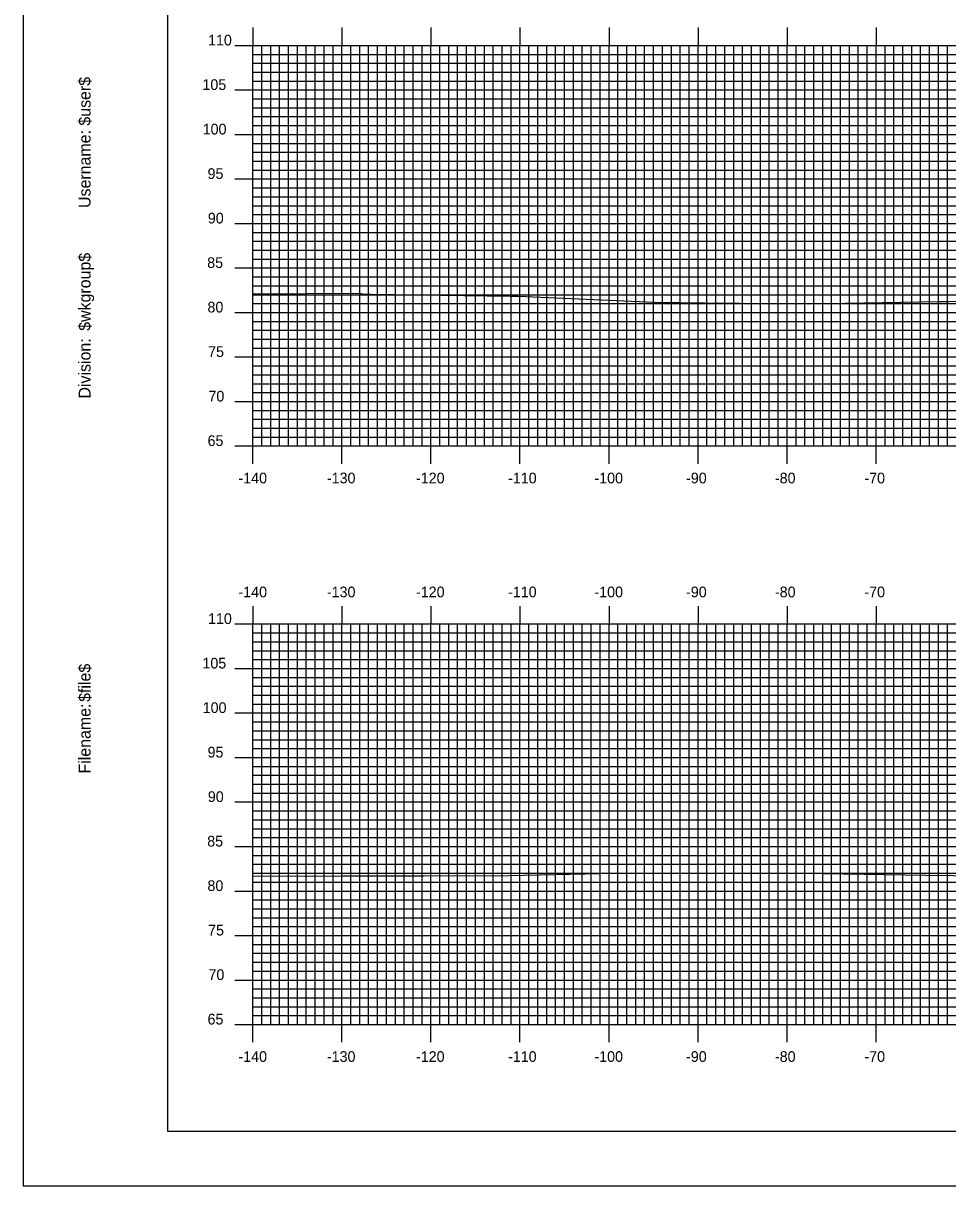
# Model space of a CAD drawing. Extents: x 857504 to 857847, y 364765 to 364985.
# Drawn here: x 857503.5 to 857607.4, y 364765.2 to 364895.8 of the extents above; entities that cross this region are included whole.
import ezdxf

# ---------------------------------------------------------------- set-up
doc = ezdxf.new("R2010")
doc.units = 0
for name, color, linetype in [('BORDER', 7, 'Continuous'), ('D_Roadway_Centerline', 7, 'Continuous'), ('H_V ANNOTATION', 7, 'Continuous'), ('MAJOR', 7, 'Continuous'), ('MINOR', 7, 'Continuous'), ('PLOT BOUNDARY', 7, 'Continuous'), ('S_Roadway_Centerline', 7, 'Continuous')]:
    doc.layers.add(name, color=color, linetype=linetype)

msp = doc.modelspace()

# ---------------------------------------------------------------- linework, layer by layer
at = {"layer": 'BORDER'}
msp.add_lwpolyline([(857519.71, 364771.3), (857839.71, 364771.3), (857839.71, 364981.3), (857519.71, 364981.3)], close=True, dxfattribs=at)
at = {"layer": 'MAJOR'}
for p, q in [((857529.31, 364895.31), (857529.31, 364893.3)), ((857539.31, 364895.31), (857539.31, 364893.3)), ((857549.31, 364895.31), (857549.31, 364893.3)), ((857559.31, 364895.31), (857559.31, 364893.3)), ((857569.31, 364895.31), (857569.31, 364893.3)), ((857579.31, 364895.31), (857579.31, 364893.3)), ((857589.31, 364895.31), (857589.31, 364893.3)), ((857599.31, 364895.31), (857599.31, 364893.3)), ((857527.3, 364893.3), (857529.31, 364893.3)), ((857529.31, 364893.3), (857809.31, 364893.3)), ((857529.31, 364848.3), (857529.31, 364893.3)), ((857529.31, 364848.3), (857529.31, 364893.3)), ((857529.31, 364893.3), (857809.31, 364893.3)), ((857539.31, 364848.3), (857539.31, 364893.3)), ((857549.31, 364848.3), (857549.31, 364893.3)), ((857559.31, 364848.3), (857559.31, 364893.3)), ((857569.31, 364848.3), (857569.31, 364893.3)), ((857579.31, 364848.3), (857579.31, 364893.3)), ((857589.31, 364848.3), (857589.31, 364893.3)), ((857599.31, 364848.3), (857599.31, 364893.3)), ((857527.3, 364888.3), (857529.31, 364888.3)), ((857529.31, 364888.3), (857809.31, 364888.3)), ((857527.3, 364883.3), (857529.31, 364883.3)), ((857529.31, 364883.3), (857809.31, 364883.3)), ((857527.3, 364878.3), (857529.31, 364878.3)), ((857529.31, 364878.3), (857809.31, 364878.3)), ((857527.3, 364873.3), (857529.31, 364873.3)), ((857529.31, 364873.3), (857809.31, 364873.3)), ((857527.3, 364868.3), (857529.31, 364868.3)), ((857529.31, 364868.3), (857809.31, 364868.3)), ((857527.3, 364863.3), (857529.31, 364863.3)), ((857529.31, 364863.3), (857809.31, 364863.3)), ((857527.3, 364858.3), (857529.31, 364858.3)), ((857529.31, 364858.3), (857809.31, 364858.3)), ((857527.3, 364853.3), (857529.31, 364853.3)), ((857529.31, 364853.3), (857809.31, 364853.3)), ((857527.3, 364848.3), (857529.31, 364848.3)), ((857529.31, 364848.3), (857809.31, 364848.3)), ((857529.31, 364848.3), (857809.31, 364848.3)), ((857529.31, 364846.3), (857529.31, 364848.3)), ((857539.31, 364846.3), (857539.31, 364848.3)), ((857549.31, 364846.3), (857549.31, 364848.3)), ((857559.31, 364846.3), (857559.31, 364848.3)), ((857569.31, 364846.3), (857569.31, 364848.3)), ((857579.31, 364846.3), (857579.31, 364848.3)), ((857589.31, 364846.3), (857589.31, 364848.3)), ((857599.31, 364846.3), (857599.31, 364848.3)), ((857529.31, 364830.31), (857529.31, 364828.3)), ((857539.31, 364830.31), (857539.31, 364828.3)), ((857549.31, 364830.31), (857549.31, 364828.3)), ((857559.31, 364830.31), (857559.31, 364828.3)), ((857569.31, 364830.31), (857569.31, 364828.3)), ((857579.31, 364830.31), (857579.31, 364828.3)), ((857589.31, 364830.31), (857589.31, 364828.3)), ((857599.31, 364830.31), (857599.31, 364828.3)), ((857527.3, 364828.3), (857529.31, 364828.3)), ((857529.31, 364828.3), (857809.31, 364828.3)), ((857529.31, 364783.3), (857529.31, 364828.3)), ((857529.31, 364783.3), (857529.31, 364828.3)), ((857529.31, 364828.3), (857809.31, 364828.3)), ((857539.31, 364783.3), (857539.31, 364828.3)), ((857549.31, 364783.3), (857549.31, 364828.3)), ((857559.31, 364783.3), (857559.31, 364828.3)), ((857569.31, 364783.3), (857569.31, 364828.3)), ((857579.31, 364783.3), (857579.31, 364828.3)), ((857589.31, 364783.3), (857589.31, 364828.3)), ((857599.31, 364783.3), (857599.31, 364828.3)), ((857527.3, 364823.3), (857529.31, 364823.3)), ((857529.31, 364823.3), (857809.31, 364823.3)), ((857527.3, 364818.3), (857529.31, 364818.3)), ((857529.31, 364818.3), (857809.31, 364818.3)), ((857527.3, 364813.3), (857529.31, 364813.3)), ((857529.31, 364813.3), (857809.31, 364813.3)), ((857527.3, 364808.3), (857529.31, 364808.3)), ((857529.31, 364808.3), (857809.31, 364808.3)), ((857527.3, 364803.3), (857529.31, 364803.3)), ((857529.31, 364803.3), (857809.31, 364803.3)), ((857527.3, 364798.3), (857529.31, 364798.3)), ((857529.31, 364798.3), (857809.31, 364798.3)), ((857527.3, 364793.3), (857529.31, 364793.3)), ((857529.31, 364793.3), (857809.31, 364793.3)), ((857527.3, 364788.3), (857529.31, 364788.3)), ((857529.31, 364788.3), (857809.31, 364788.3)), ((857527.3, 364783.3), (857529.31, 364783.3)), ((857529.31, 364783.3), (857809.31, 364783.3)), ((857529.31, 364783.3), (857809.31, 364783.3)), ((857529.31, 364781.3), (857529.31, 364783.3)), ((857539.31, 364781.3), (857539.31, 364783.3)), ((857549.31, 364781.3), (857549.31, 364783.3)), ((857559.31, 364781.3), (857559.31, 364783.3)), ((857569.31, 364781.3), (857569.31, 364783.3)), ((857579.31, 364781.3), (857579.31, 364783.3)), ((857589.31, 364781.3), (857589.31, 364783.3)), ((857599.31, 364781.3), (857599.31, 364783.3))]:
    msp.add_line(p, q, dxfattribs=at)
at = {"layer": 'MINOR'}
for p, q in [((857530.31, 364848.3), (857530.31, 364893.3)), ((857531.31, 364848.3), (857531.31, 364893.3)), ((857532.31, 364848.3), (857532.31, 364893.3)), ((857533.31, 364848.3), (857533.31, 364893.3)), ((857534.31, 364848.3), (857534.31, 364893.3)), ((857535.31, 364848.3), (857535.31, 364893.3)), ((857536.31, 364848.3), (857536.31, 364893.3)), ((857537.31, 364848.3), (857537.31, 364893.3)), ((857538.31, 364848.3), (857538.31, 364893.3)), ((857540.31, 364848.3), (857540.31, 364893.3)), ((857541.31, 364848.3), (857541.31, 364893.3)), ((857542.31, 364848.3), (857542.31, 364893.3)), ((857543.31, 364848.3), (857543.31, 364893.3)), ((857544.31, 364848.3), (857544.31, 364893.3)), ((857545.31, 364848.3), (857545.31, 364893.3)), ((857546.31, 364848.3), (857546.31, 364893.3)), ((857547.31, 364848.3), (857547.31, 364893.3)), ((857548.31, 364848.3), (857548.31, 364893.3)), ((857550.31, 364848.3), (857550.31, 364893.3)), ((857551.31, 364848.3), (857551.31, 364893.3)), ((857552.31, 364848.3), (857552.31, 364893.3)), ((857553.31, 364848.3), (857553.31, 364893.3)), ((857554.31, 364848.3), (857554.31, 364893.3)), ((857555.31, 364848.3), (857555.31, 364893.3)), ((857556.31, 364848.3), (857556.31, 364893.3)), ((857557.31, 364848.3), (857557.31, 364893.3)), ((857558.31, 364848.3), (857558.31, 364893.3)), ((857560.31, 364848.3), (857560.31, 364893.3)), ((857561.31, 364848.3), (857561.31, 364893.3)), ((857562.31, 364848.3), (857562.31, 364893.3)), ((857563.31, 364848.3), (857563.31, 364893.3)), ((857564.31, 364848.3), (857564.31, 364893.3)), ((857565.31, 364848.3), (857565.31, 364893.3)), ((857566.31, 364848.3), (857566.31, 364893.3)), ((857567.31, 364848.3), (857567.31, 364893.3)), ((857568.31, 364848.3), (857568.31, 364893.3)), ((857570.31, 364848.3), (857570.31, 364893.3)), ((857571.31, 364848.3), (857571.31, 364893.3)), ((857572.31, 364848.3), (857572.31, 364893.3)), ((857573.31, 364848.3), (857573.31, 364893.3)), ((857574.31, 364848.3), (857574.31, 364893.3)), ((857575.31, 364848.3), (857575.31, 364893.3)), ((857576.31, 364848.3), (857576.31, 364893.3)), ((857577.31, 364848.3), (857577.31, 364893.3)), ((857578.31, 364848.3), (857578.31, 364893.3)), ((857580.31, 364848.3), (857580.31, 364893.3)), ((857581.31, 364848.3), (857581.31, 364893.3)), ((857582.31, 364848.3), (857582.31, 364893.3)), ((857583.31, 364848.3), (857583.31, 364893.3)), ((857584.31, 364848.3), (857584.31, 364893.3)), ((857585.31, 364848.3), (857585.31, 364893.3)), ((857586.31, 364848.3), (857586.31, 364893.3)), ((857587.31, 364848.3), (857587.31, 364893.3)), ((857588.31, 364848.3), (857588.31, 364893.3)), ((857590.31, 364848.3), (857590.31, 364893.3)), ((857591.31, 364848.3), (857591.31, 364893.3)), ((857592.31, 364848.3), (857592.31, 364893.3)), ((857593.31, 364848.3), (857593.31, 364893.3)), ((857594.31, 364848.3), (857594.31, 364893.3)), ((857595.31, 364848.3), (857595.31, 364893.3)), ((857596.31, 364848.3), (857596.31, 364893.3)), ((857597.31, 364848.3), (857597.31, 364893.3)), ((857598.31, 364848.3), (857598.31, 364893.3)), ((857600.31, 364848.3), (857600.31, 364893.3)), ((857601.31, 364848.3), (857601.31, 364893.3)), ((857602.31, 364848.3), (857602.31, 364893.3)), ((857603.31, 364848.3), (857603.31, 364893.3)), ((857604.31, 364848.3), (857604.31, 364893.3)), ((857605.31, 364848.3), (857605.31, 364893.3)), ((857606.31, 364848.3), (857606.31, 364893.3)), ((857607.31, 364848.3), (857607.31, 364893.3)), ((857529.31, 364892.3), (857809.31, 364892.3)), ((857529.31, 364892.3), (857531.31, 364892.3)), ((857529.31, 364891.3), (857809.31, 364891.3)), ((857529.31, 364891.3), (857531.31, 364891.3)), ((857529.31, 364890.3), (857809.31, 364890.3)), ((857529.31, 364890.3), (857531.31, 364890.3)), ((857529.31, 364889.3), (857809.31, 364889.3)), ((857529.31, 364889.3), (857531.31, 364889.3)), ((857529.31, 364887.3), (857809.31, 364887.3)), ((857529.31, 364887.3), (857531.31, 364887.3)), ((857529.31, 364886.3), (857809.31, 364886.3)), ((857529.31, 364886.3), (857531.31, 364886.3)), ((857529.31, 364885.3), (857809.31, 364885.3)), ((857529.31, 364885.3), (857531.31, 364885.3)), ((857529.31, 364884.3), (857809.31, 364884.3)), ((857529.31, 364884.3), (857531.31, 364884.3)), ((857529.31, 364882.3), (857809.31, 364882.3)), ((857529.31, 364882.3), (857531.31, 364882.3)), ((857529.31, 364881.3), (857809.31, 364881.3)), ((857529.31, 364881.3), (857531.31, 364881.3)), ((857529.31, 364880.3), (857809.31, 364880.3)), ((857529.31, 364880.3), (857531.31, 364880.3)), ((857529.31, 364879.3), (857809.31, 364879.3)), ((857529.31, 364879.3), (857531.31, 364879.3)), ((857529.31, 364877.3), (857809.31, 364877.3)), ((857529.31, 364877.3), (857531.31, 364877.3)), ((857529.31, 364876.3), (857809.31, 364876.3)), ((857529.31, 364876.3), (857531.31, 364876.3)), ((857529.31, 364875.3), (857809.31, 364875.3)), ((857529.31, 364875.3), (857531.31, 364875.3)), ((857529.31, 364874.3), (857809.31, 364874.3)), ((857529.31, 364874.3), (857531.31, 364874.3)), ((857529.31, 364872.3), (857809.31, 364872.3)), ((857529.31, 364872.3), (857531.31, 364872.3)), ((857529.31, 364871.3), (857809.31, 364871.3)), ((857529.31, 364871.3), (857531.31, 364871.3)), ((857529.31, 364870.3), (857809.31, 364870.3)), ((857529.31, 364870.3), (857531.31, 364870.3)), ((857529.31, 364869.3), (857809.31, 364869.3)), ((857529.31, 364869.3), (857531.31, 364869.3)), ((857529.31, 364867.3), (857809.31, 364867.3)), ((857529.31, 364867.3), (857531.31, 364867.3)), ((857529.31, 364866.3), (857809.31, 364866.3)), ((857529.31, 364866.3), (857531.31, 364866.3)), ((857529.31, 364865.3), (857809.31, 364865.3)), ((857529.31, 364865.3), (857531.31, 364865.3)), ((857529.31, 364864.3), (857809.31, 364864.3)), ((857529.31, 364864.3), (857531.31, 364864.3)), ((857529.31, 364862.3), (857809.31, 364862.3)), ((857529.31, 364862.3), (857531.31, 364862.3)), ((857529.31, 364861.3), (857809.31, 364861.3)), ((857529.31, 364861.3), (857531.31, 364861.3)), ((857529.31, 364860.3), (857809.31, 364860.3)), ((857529.31, 364860.3), (857531.31, 364860.3)), ((857529.31, 364859.3), (857809.31, 364859.3)), ((857529.31, 364859.3), (857531.31, 364859.3)), ((857529.31, 364857.3), (857809.31, 364857.3)), ((857529.31, 364857.3), (857531.31, 364857.3)), ((857529.31, 364856.3), (857809.31, 364856.3)), ((857529.31, 364856.3), (857531.31, 364856.3)), ((857529.31, 364855.3), (857809.31, 364855.3)), ((857529.31, 364855.3), (857531.31, 364855.3)), ((857529.31, 364854.3), (857809.31, 364854.3)), ((857529.31, 364854.3), (857531.31, 364854.3)), ((857529.31, 364852.3), (857809.31, 364852.3)), ((857529.31, 364852.3), (857531.31, 364852.3)), ((857529.31, 364851.3), (857809.31, 364851.3)), ((857529.31, 364851.3), (857531.31, 364851.3)), ((857529.31, 364850.3), (857809.31, 364850.3)), ((857529.31, 364850.3), (857531.31, 364850.3)), ((857529.31, 364849.3), (857809.31, 364849.3)), ((857529.31, 364849.3), (857531.31, 364849.3)), ((857530.31, 364783.3), (857530.31, 364828.3)), ((857531.31, 364783.3), (857531.31, 364828.3)), ((857532.31, 364783.3), (857532.31, 364828.3)), ((857533.31, 364783.3), (857533.31, 364828.3)), ((857534.31, 364783.3), (857534.31, 364828.3)), ((857535.31, 364783.3), (857535.31, 364828.3)), ((857536.31, 364783.3), (857536.31, 364828.3)), ((857537.31, 364783.3), (857537.31, 364828.3)), ((857538.31, 364783.3), (857538.31, 364828.3)), ((857540.31, 364783.3), (857540.31, 364828.3)), ((857541.31, 364783.3), (857541.31, 364828.3)), ((857542.31, 364783.3), (857542.31, 364828.3)), ((857543.31, 364783.3), (857543.31, 364828.3)), ((857544.31, 364783.3), (857544.31, 364828.3)), ((857545.31, 364783.3), (857545.31, 364828.3)), ((857546.31, 364783.3), (857546.31, 364828.3)), ((857547.31, 364783.3), (857547.31, 364828.3)), ((857548.31, 364783.3), (857548.31, 364828.3)), ((857550.31, 364783.3), (857550.31, 364828.3)), ((857551.31, 364783.3), (857551.31, 364828.3)), ((857552.31, 364783.3), (857552.31, 364828.3)), ((857553.31, 364783.3), (857553.31, 364828.3)), ((857554.31, 364783.3), (857554.31, 364828.3)), ((857555.31, 364783.3), (857555.31, 364828.3)), ((857556.31, 364783.3), (857556.31, 364828.3)), ((857557.31, 364783.3), (857557.31, 364828.3)), ((857558.31, 364783.3), (857558.31, 364828.3)), ((857560.31, 364783.3), (857560.31, 364828.3)), ((857561.31, 364783.3), (857561.31, 364828.3)), ((857562.31, 364783.3), (857562.31, 364828.3)), ((857563.31, 364783.3), (857563.31, 364828.3)), ((857564.31, 364783.3), (857564.31, 364828.3)), ((857565.31, 364783.3), (857565.31, 364828.3)), ((857566.31, 364783.3), (857566.31, 364828.3)), ((857567.31, 364783.3), (857567.31, 364828.3)), ((857568.31, 364783.3), (857568.31, 364828.3)), ((857570.31, 364783.3), (857570.31, 364828.3)), ((857571.31, 364783.3), (857571.31, 364828.3)), ((857572.31, 364783.3), (857572.31, 364828.3)), ((857573.31, 364783.3), (857573.31, 364828.3)), ((857574.31, 364783.3), (857574.31, 364828.3)), ((857575.31, 364783.3), (857575.31, 364828.3)), ((857576.31, 364783.3), (857576.31, 364828.3)), ((857577.31, 364783.3), (857577.31, 364828.3)), ((857578.31, 364783.3), (857578.31, 364828.3)), ((857580.31, 364783.3), (857580.31, 364828.3)), ((857581.31, 364783.3), (857581.31, 364828.3)), ((857582.31, 364783.3), (857582.31, 364828.3)), ((857583.31, 364783.3), (857583.31, 364828.3)), ((857584.31, 364783.3), (857584.31, 364828.3)), ((857585.31, 364783.3), (857585.31, 364828.3)), ((857586.31, 364783.3), (857586.31, 364828.3)), ((857587.31, 364783.3), (857587.31, 364828.3)), ((857588.31, 364783.3), (857588.31, 364828.3)), ((857590.31, 364783.3), (857590.31, 364828.3)), ((857591.31, 364783.3), (857591.31, 364828.3)), ((857592.31, 364783.3), (857592.31, 364828.3)), ((857593.31, 364783.3), (857593.31, 364828.3)), ((857594.31, 364783.3), (857594.31, 364828.3)), ((857595.31, 364783.3), (857595.31, 364828.3)), ((857596.31, 364783.3), (857596.31, 364828.3)), ((857597.31, 364783.3), (857597.31, 364828.3)), ((857598.31, 364783.3), (857598.31, 364828.3)), ((857600.31, 364783.3), (857600.31, 364828.3)), ((857601.31, 364783.3), (857601.31, 364828.3)), ((857602.31, 364783.3), (857602.31, 364828.3)), ((857603.31, 364783.3), (857603.31, 364828.3)), ((857604.31, 364783.3), (857604.31, 364828.3)), ((857605.31, 364783.3), (857605.31, 364828.3)), ((857606.31, 364783.3), (857606.31, 364828.3)), ((857607.31, 364783.3), (857607.31, 364828.3)), ((857529.31, 364827.3), (857809.31, 364827.3)), ((857529.31, 364827.3), (857531.31, 364827.3)), ((857529.31, 364826.3), (857809.31, 364826.3)), ((857529.31, 364826.3), (857531.31, 364826.3)), ((857529.31, 364825.3), (857809.31, 364825.3)), ((857529.31, 364825.3), (857531.31, 364825.3)), ((857529.31, 364824.3), (857809.31, 364824.3)), ((857529.31, 364824.3), (857531.31, 364824.3)), ((857529.31, 364822.3), (857809.31, 364822.3)), ((857529.31, 364822.3), (857531.31, 364822.3)), ((857529.31, 364821.3), (857809.31, 364821.3)), ((857529.31, 364821.3), (857531.31, 364821.3)), ((857529.31, 364820.3), (857809.31, 364820.3)), ((857529.31, 364820.3), (857531.31, 364820.3)), ((857529.31, 364819.3), (857809.31, 364819.3)), ((857529.31, 364819.3), (857531.31, 364819.3)), ((857529.31, 364817.3), (857809.31, 364817.3)), ((857529.31, 364817.3), (857531.31, 364817.3)), ((857529.31, 364816.3), (857809.31, 364816.3)), ((857529.31, 364816.3), (857531.31, 364816.3)), ((857529.31, 364815.3), (857809.31, 364815.3)), ((857529.31, 364815.3), (857531.31, 364815.3)), ((857529.31, 364814.3), (857809.31, 364814.3)), ((857529.31, 364814.3), (857531.31, 364814.3)), ((857529.31, 364812.3), (857809.31, 364812.3)), ((857529.31, 364812.3), (857531.31, 364812.3)), ((857529.31, 364811.3), (857809.31, 364811.3)), ((857529.31, 364811.3), (857531.31, 364811.3)), ((857529.31, 364810.3), (857809.31, 364810.3)), ((857529.31, 364810.3), (857531.31, 364810.3)), ((857529.31, 364809.3), (857809.31, 364809.3)), ((857529.31, 364809.3), (857531.31, 364809.3)), ((857529.31, 364807.3), (857809.31, 364807.3)), ((857529.31, 364807.3), (857531.31, 364807.3)), ((857529.31, 364806.3), (857809.31, 364806.3)), ((857529.31, 364806.3), (857531.31, 364806.3)), ((857529.31, 364805.3), (857809.31, 364805.3)), ((857529.31, 364805.3), (857531.31, 364805.3)), ((857529.31, 364804.3), (857809.31, 364804.3)), ((857529.31, 364804.3), (857531.31, 364804.3)), ((857529.31, 364802.3), (857809.31, 364802.3)), ((857529.31, 364802.3), (857531.31, 364802.3)), ((857529.31, 364801.3), (857809.31, 364801.3)), ((857529.31, 364801.3), (857531.31, 364801.3)), ((857529.31, 364800.3), (857809.31, 364800.3)), ((857529.31, 364800.3), (857531.31, 364800.3)), ((857529.31, 364799.3), (857809.31, 364799.3)), ((857529.31, 364799.3), (857531.31, 364799.3)), ((857529.31, 364797.3), (857809.31, 364797.3)), ((857529.31, 364797.3), (857531.31, 364797.3)), ((857529.31, 364796.3), (857809.31, 364796.3)), ((857529.31, 364796.3), (857531.31, 364796.3)), ((857529.31, 364795.3), (857809.31, 364795.3)), ((857529.31, 364795.3), (857531.31, 364795.3)), ((857529.31, 364794.3), (857809.31, 364794.3)), ((857529.31, 364794.3), (857531.31, 364794.3)), ((857529.31, 364792.3), (857809.31, 364792.3)), ((857529.31, 364792.3), (857531.31, 364792.3)), ((857529.31, 364791.3), (857809.31, 364791.3)), ((857529.31, 364791.3), (857531.31, 364791.3)), ((857529.31, 364790.3), (857809.31, 364790.3)), ((857529.31, 364790.3), (857531.31, 364790.3)), ((857529.31, 364789.3), (857809.31, 364789.3)), ((857529.31, 364789.3), (857531.31, 364789.3)), ((857529.31, 364787.3), (857809.31, 364787.3)), ((857529.31, 364787.3), (857531.31, 364787.3)), ((857529.31, 364786.3), (857809.31, 364786.3)), ((857529.31, 364786.3), (857531.31, 364786.3)), ((857529.31, 364785.3), (857809.31, 364785.3)), ((857529.31, 364785.3), (857531.31, 364785.3)), ((857529.31, 364784.3), (857809.31, 364784.3)), ((857529.31, 364784.3), (857531.31, 364784.3))]:
    msp.add_line(p, q, dxfattribs=at)
at = {"layer": 'PLOT BOUNDARY'}
msp.add_lwpolyline([(857503.52, 364765.18), (857843.52, 364765.18), (857843.52, 364985.18), (857503.52, 364985.18)], close=True, dxfattribs=at)
at = {"layer": 'S_Roadway_Centerline'}
for points in [[(857529.31, 364865.38), (857541.18, 364865.47), (857541.94, 364865.37), (857542.6, 364865.37), (857558.19, 364865.15), (857559.11, 364865.15), (857574.38, 364864.47), (857580.05, 364864.38), (857591.66, 364864.26), (857606.23, 364864.54), (857607.47, 364864.55), (857622.56, 364864.57), (857624, 364864.58), (857625.56, 364864.56), (857654.85, 364864.2), (857657.11, 364864.21), (857659.9, 364864.19), (857673.26, 364864.14), (857685.86, 364864.25), (857689.08, 364864.25), (857695.45, 364863.91), (857705.29, 364863.35), (857718.85, 364863.53), (857729.19, 364863.55)], [(857529.31, 364800.01), (857535.41, 364799.98), (857539.24, 364800.02), (857548.54, 364800.01), (857554.53, 364800.03), (857556.35, 364800), (857571.81, 364800.35), (857586.33, 364800.27), (857589.48, 364800.32), (857593.37, 364800.28), (857604.88, 364800.09), (857614.12, 364799.97)]]:
    msp.add_lwpolyline(points, dxfattribs=at)

# ---------------------------------------------------------------- texts
at = {"layer": 'BORDER'}
for s, p in [('$user$', (857511.08, 364884.29)), ('Username:', (857511.08, 364875.04)), ('$wkgroup$', (857511.08, 364861.24)), ('Division:', (857511.08, 364853.63)), ('$file$', (857511.08, 364819.55)), ('Filename:', (857511.08, 364811.5))]:
    msp.add_text(s, height=1.339, rotation=90, dxfattribs=at).set_placement(p)
at = {"layer": 'D_Roadway_Centerline'}
for s, p in [('C', (857542.01, 364886.2)), ('L', (857542.02, 364886.19))]:
    msp.add_text(s, height=0.0146, dxfattribs=at).set_placement(p)
at = {"layer": 'H_V ANNOTATION'}
for s, p in [('110', (857524.27, 364893.3)), ('105', (857523.64, 364888.3)), ('100', (857523.67, 364883.3)), ('95', (857524.22, 364878.3)), ('90', (857524.25, 364873.3)), ('85', (857524.18, 364868.3)), ('80', (857524.21, 364863.3)), ('75', (857524.28, 364858.3)), ('70', (857524.32, 364853.3)), ('65', (857524.22, 364848.3)), ('-140', (857527.69, 364844.1)), ('-130', (857537.62, 364844.1)), ('-120', (857547.63, 364844.1)), ('-110', (857557.97, 364844.1)), ('-100', (857567.67, 364844.1)), ('-90', (857577.96, 364844.1)), ('-80', (857587.94, 364844.1)), ('-70', (857597.99, 364844.1)), ('-140', (857527.69, 364831.3)), ('-130', (857537.62, 364831.3)), ('-120', (857547.63, 364831.3)), ('-110', (857557.97, 364831.3)), ('-100', (857567.67, 364831.3)), ('-90', (857577.96, 364831.3)), ('-80', (857587.94, 364831.3)), ('-70', (857597.99, 364831.3)), ('110', (857524.27, 364828.3)), ('105', (857523.64, 364823.3)), ('100', (857523.67, 364818.3)), ('95', (857524.22, 364813.3)), ('90', (857524.25, 364808.3)), ('85', (857524.18, 364803.3)), ('80', (857524.21, 364798.3)), ('75', (857524.28, 364793.3)), ('70', (857524.32, 364788.3)), ('65', (857524.22, 364783.3)), ('-140', (857527.69, 364779.1)), ('-130', (857537.62, 364779.1)), ('-120', (857547.63, 364779.1)), ('-110', (857557.97, 364779.1)), ('-100', (857567.67, 364779.1)), ('-90', (857577.96, 364779.1)), ('-80', (857587.94, 364779.1)), ('-70', (857597.99, 364779.1))]:
    msp.add_text(s, height=1.2, dxfattribs=at).set_placement(p)
at = {"layer": 'MAJOR'}
for p in [(857529.3, 364848.3), (857529.3, 364783.3)]:
    msp.add_text('-', height=0.012, dxfattribs=at).set_placement(p)

doc.saveas('drawing.dxf')
